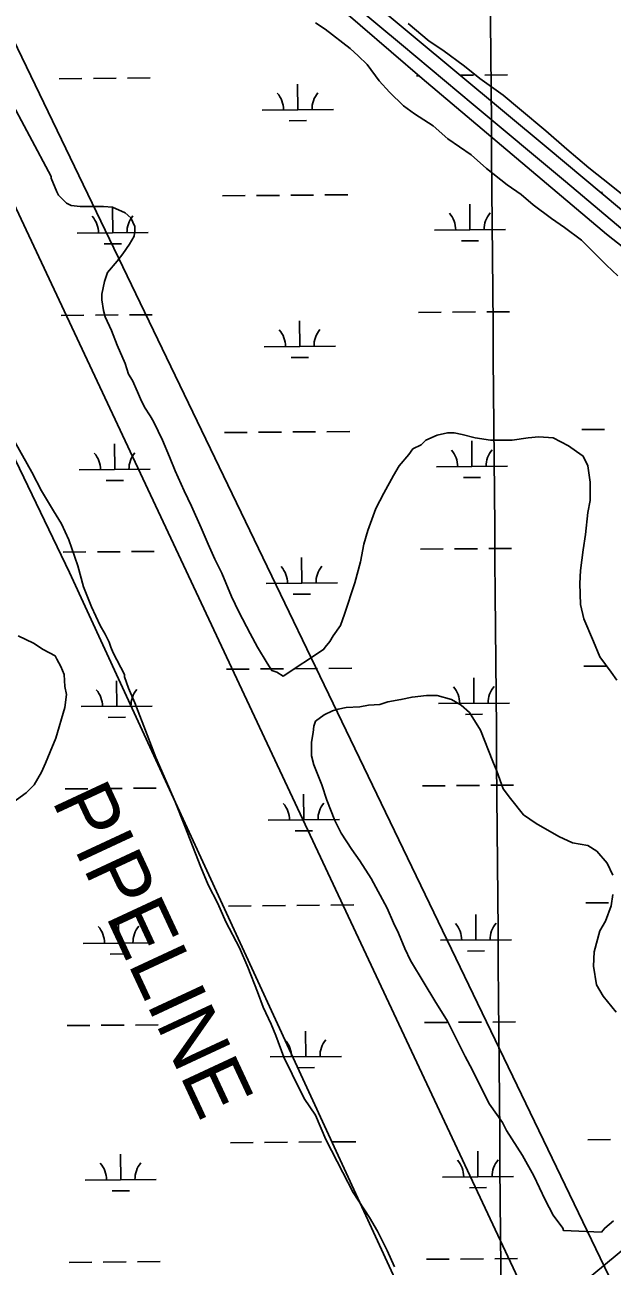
# Model space of a CAD drawing. Extents: x 3568792 to 3606828, y 529143 to 554785.
# Drawn here: x 3580902 to 3581727, y 542432 to 544177 of the extents above; entities that cross this region are included whole.
import ezdxf

# ---------------------------------------------------------------- set-up
doc = ezdxf.new("R2010")
doc.units = 0
for name, color, linetype in [('V-GRID-MAJR', 7, 'Continuous'), ('V-RAIL-TRAK', 7, 'Continuous'), ('V-SITE-VEGE', 7, 'Continuous'), ('V-UTIL-IDEN', 7, 'Continuous'), ('V-UTIL-LINE', 7, 'Continuous'), ('V-WETL-SWMP', 7, 'Continuous')]:
    doc.layers.add(name, color=color, linetype=linetype)

msp = doc.modelspace()

# ---------------------------------------------------------------- linework, layer by layer
at = {"layer": 'V-GRID-MAJR'}
msp.add_spline([(3581635.663, 534620.355), (3581585.44, 540678.077), (3581535.1920000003, 546738.885), (3581484.943, 552799.707), (3581484.918, 552802.775)], degree=3, dxfattribs=at)
at = {"layer": 'V-RAIL-TRAK'}
msp.add_lwpolyline([(3580851.771, 544633.429), (3580996.5270000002, 544512.45), (3581029.0840000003, 544485.449), (3581051.832, 544466.243), (3581133.9560000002, 544398.343), (3581292.914, 544264.992), (3581431.258, 544149.052), (3581532.038, 544064.734), (3581661.679, 543956.585), (3581805.061, 543836.0650000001), (3581938.3680000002, 543725.6240000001), (3582066.177, 543626.64), (3582144.055, 543569.356), (3582211.397, 543523.528)], dxfattribs=at)
at = {"layer": 'V-SITE-VEGE'}
for points in [[(3581310.598, 544179.824), (3581324.183, 544170.763), (3581359.279, 544143.584), (3581370.6010000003, 544133.395), (3581383.0530000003, 544120.9400000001), (3581400.0330000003, 544098.2930000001), (3581414.7490000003, 544082.439), (3581433.997, 544063.188), (3581449.846, 544051.865), (3581475.884, 544034.878), (3581496.264, 544016.758), (3581529.091, 543994.111), (3581550.6040000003, 543974.86), (3581580.039, 543952.213), (3581599.287, 543938.625), (3581616.267, 543923.903), (3581642.307, 543904.652), (3581660.419, 543892.194), (3581684.1950000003, 543874.076), (3581719.287, 543838.973), (3581735.139, 543824.252)], [(3581782.701, 543905.768), (3581726.097, 543951.062), (3581694.398, 543975.976), (3581663.829, 544002.02), (3581634.395, 544028.0650000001), (3581597.036, 544058.639), (3581574.393, 544077.893), (3581541.562, 544101.672), (3581520.052, 544118.654), (3581489.485, 544141.307), (3581470.238, 544153.763), (3581440.804, 544178.675)], [(3581420.345, 543543.5), (3581406.754, 543518.5920000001), (3581395.431, 543497.082), (3581384.103, 543466.511), (3581378.441, 543447.264), (3581373.9080000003, 543422.356), (3581365.98, 543392.919), (3581351.255, 543348.764), (3581345.593, 543332.912), (3581335.4, 543318.1950000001), (3581330.87, 543310.2710000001), (3581324.074, 543302.346), (3581321.811, 543298.95), (3581265.194, 543261.595), (3581256.1380000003, 543267.255), (3581249.345, 543269.52), (3581242.554, 543279.711), (3581228.969, 543302.358), (3581218.778, 543321.607), (3581202.933, 543352.18), (3581192.748, 543373.694), (3581179.164, 543406.53), (3581168.975, 543425.779), (3581159.921, 543447.2930000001), (3581149.734, 543469.938), (3581136.1520000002, 543500.508), (3581125.963, 543522.022), (3581113.511, 543550.33), (3581105.59, 543569.579), (3581095.403, 543593.356), (3581089.742, 543605.812), (3581082.951, 543619.399), (3581078.423, 543627.326), (3581070.4990000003, 543639.78), (3581064.838, 543651.104), (3581060.3140000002, 543661.295), (3581053.519, 543677.1460000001), (3581047.861, 543686.204), (3581043.332, 543700.925), (3581032.015, 543726.968), (3581024.091, 543747.349), (3581015.035, 543766.5970000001), (3581012.772, 543775.657), (3581010.509, 543790.376), (3581010.511, 543798.3), (3581013.909, 543816.416), (3581018.441, 543828.87), (3581032.029, 543844.72), (3581039.955, 543854.908), (3581049.0160000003, 543868.495), (3581055.809, 543879.814), (3581056.9450000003, 543887.742), (3581056.9450000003, 543893.403), (3581051.285, 543905.854), (3581043.359, 543912.652), (3581025.242, 543920.58), (3581012.791, 543921.712), (3580979.955, 543921.716), (3580967.501, 543922.851), (3580960.708, 543926.248), (3580949.389, 543937.572), (3580947.1240000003, 543942.102), (3580939.2, 543961.349), (3580939.202, 543963.6140000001), (3580878.075, 544077.977)], [(3580819.156, 543737.183), (3580823.684, 543731.523), (3580832.7430000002, 543722.462), (3580842.927, 543696.422), (3580853.116, 543672.643), (3580873.49, 543621.6900000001), (3580888.205, 543591.118), (3580911.9760000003, 543548.091), (3580925.558, 543522.049), (3580942.538, 543493.74), (3580953.859, 543475.623), (3580964.046, 543452.976), (3580976.498, 543416.745), (3580984.4220000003, 543387.305)], [(3581733.936, 543255.875), (3581726.0130000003, 543267.198), (3581710.161, 543288.712), (3581701.107, 543310.224), (3581687.525, 543341.929), (3581682.9990000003, 543362.309), (3581681.87, 543391.747), (3581683.005, 543409.8640000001), (3581686.404, 543439.302), (3581689.804, 543460.816), (3581693.2060000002, 543491.382), (3581696.603, 543508.366), (3581696.608, 543534.407), (3581693.214, 543557.051), (3581686.423, 543570.64), (3581677.365, 543577.433), (3581666.043, 543585.361), (3581644.531, 543596.686), (3581624.151, 543597.821), (3581609.432, 543596.6900000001), (3581586.788, 543593.297), (3581556.217, 543593.301), (3581534.707, 543596.699), (3581516.59, 543601.231), (3581505.269, 543603.496), (3581496.213, 543603.498), (3581481.492, 543600.102), (3581465.64, 543593.311), (3581458.845, 543586.518), (3581447.524, 543580.859), (3581441.861, 543572.934), (3581428.272, 543557.084), (3581420.345, 543543.5)], [(3580984.4220000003, 543387.305), (3580995.737, 543358.997), (3581008.1890000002, 543332.955), (3581014.98, 543320.4990000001), (3581020.6410000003, 543309.178), (3581022.904, 543302.385), (3581026.299, 543294.459), (3581042.147, 543263.886), (3581042.147, 543260.4890000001), (3581047.805, 543244.637), (3581056.861, 543224.255), (3581073.839, 543178.966), (3581086.289, 543147.261), (3581104.4, 543105.365), (3581113.4560000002, 543084.987), (3581127.036, 543051.017), (3581149.6750000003, 542993.27), (3581159.862, 542968.36), (3581173.446, 542942.318), (3581184.7630000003, 542916.275), (3581204.008, 542880.042), (3581215.328, 542852.865), (3581228.91, 542817.764), (3581236.832, 542796.252), (3581248.151, 542772.475), (3581254.9420000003, 542756.621), (3581266.261, 542726.051), (3581277.5810000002, 542702.2710000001), (3581294.561, 542668.301), (3581310.4080000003, 542644.524), (3581325.123, 542610.556), (3581348.894, 542564.132), (3581363.609, 542535.824), (3581386.25, 542500.724), (3581397.569, 542481.473), (3581411.151, 542454.2980000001), (3581421.34, 542431.653)], [(3580880.215, 543080.486), (3580903.9930000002, 543097.466), (3580915.318, 543108.785), (3580925.511, 543126.902), (3580931.174, 543139.354), (3580937.969, 543155.205), (3580945.897, 543174.452), (3580958.355, 543217.475), (3580960.622, 543235.589), (3580958.361, 543246.9130000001), (3580957.23, 543263.897), (3580952.702, 543275.22), (3580947.042, 543285.411), (3580944.779, 543289.939), (3580927.7970000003, 543298.9990000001), (3580914.21, 543308.058), (3580892.7, 543318.25)], [(3581334.255, 543212.899), (3581342.181, 543215.162), (3581353.502, 543217.425), (3581372.751, 543218.556), (3581385.205, 543220.817), (3581401.057, 543221.949), (3581412.38, 543225.345), (3581430.497, 543228.7390000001), (3581446.348, 543232.132), (3581466.728, 543234.395), (3581481.447, 543234.393), (3581501.826, 543228.73), (3581515.413, 543220.803), (3581526.732, 543210.612), (3581542.582, 543185.7), (3581559.559, 543141.541), (3581565.218, 543127.954), (3581574.272, 543103.045), (3581584.461, 543089.456), (3581602.576, 543066.809), (3581620.688, 543054.351), (3581652.389, 543036.233), (3581671.636, 543027.172), (3581693.146, 543023.773), (3581705.602, 543015.8470000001), (3581720.3170000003, 542998.861), (3581728.241, 542981.877)], [(3581729.312, 542496.151), (3581716.858, 542485.964), (3581712.328, 542480.301), (3581659.115, 542482.572), (3581657.982, 542485.97), (3581644.398, 542504.087), (3581633.079, 542525.601), (3581617.231, 542559.571), (3581601.384, 542587.878), (3581578.745, 542622.979), (3581573.082, 542634.302), (3581554.972, 542660.3470000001), (3581545.916, 542677.331), (3581531.201, 542707.901), (3581521.0100000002, 542727.151), (3581496.108, 542776.9720000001), (3581477.998, 542805.28), (3581463.281, 542830.192), (3581444.038, 542861.899), (3581436.114, 542878.881), (3581427.058, 542900.393), (3581420.267, 542915.1140000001), (3581411.211, 542935.4940000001), (3581388.574, 542977.39), (3581372.725, 543002.299), (3581361.403, 543018.153), (3581346.688, 543040.8), (3581337.632, 543058.916), (3581326.315, 543087.224), (3581319.524, 543108.736), (3581308.204, 543137.0430000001), (3581304.809, 543149.497), (3581304.811, 543168.746), (3581307.08, 543182.333), (3581308.21, 543191.389), (3581310.4760000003, 543198.182), (3581322.932, 543207.241), (3581334.255, 543212.899)], [(3581728.239, 542954.704), (3581725.972, 542938.852), (3581718.044, 542917.34), (3581710.116, 542903.756), (3581702.186, 542874.318), (3581701.052, 542853.938), (3581705.578, 542827.8960000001), (3581714.632, 542812.044), (3581732.747, 542789.397)]]:
    msp.add_lwpolyline(points, dxfattribs=at)
at = {"layer": 'V-UTIL-LINE'}
for points in [[(3576104.455, 549614.54), (3575980.615, 549380.701), (3575975.626, 549330.036), (3575795.666, 548982.226), (3575847.038, 548939.277), (3577996.318, 547114.274), (3577969.606, 547146.5380000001), (3578424.397, 546757.6410000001), (3580608.2060000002, 544894.199), (3580586.223, 544823.942), (3580566.441, 544763.821), (3580835.9560000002, 544259.362), (3581735.407, 542392.716), (3581735.411, 542392.049), (3583243.878, 539198.559), (3583455.717, 538592.296), (3583631.009, 538180.394), (3585262.885397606, 534650.9548145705)], [(3585128.275264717, 534649.8192223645), (3583719.583, 537704.209), (3582542.505, 540395.462), (3580772.2260000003, 544169.545), (3580472.688, 544757.343), (3580549.244, 544846.0480000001), (3580609.068, 544913.133), (3580567.3850000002, 544989.093), (3578476.0870000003, 546727.515), (3578101.464, 547060.86), (3578033.7660000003, 547070.019), (3577965.6780000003, 547126.361), (3576392.603, 548421.705), (3576369.895, 548541.527), (3575884.164, 548880.2660000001), (3575580.12, 549146.928), (3575181.362, 549483.568), (3575183.417, 549530.056)], [(3580613.684734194, 544136.940699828), (3580964.770032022, 543407.4351588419), (3581516.1019293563, 542211.0465516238), (3581921.2891189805, 541354.1472654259), (3582238.881483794, 540665.280643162), (3582616.1867291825, 539900.9831717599), (3582941.5330784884, 539167.7056383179), (3583265.5994303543, 538481.90100993), (3583288.6693842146, 538443.2290872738), (3583363.888233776, 538253.5674665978), (3583745.1074713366, 537485.180003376), (3584083.525794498, 536767.4394388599), (3584210.786539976, 536519.0029357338), (3584467.5920263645, 535947.402078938)]]:
    msp.add_lwpolyline(points, dxfattribs=at)
at = {"layer": 'V-WETL-SWMP'}
for p, q in [((3580950.4369965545, 544101.1577353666), (3580982.4358521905, 544101.4276837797)), ((3580998.4352800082, 544101.5626579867), (3581030.4341356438, 544101.8326063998)), ((3581046.4335634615, 544101.9675806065), (3581078.432419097, 544102.2375290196)), ((3581285.660710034, 544057.5540968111), (3581285.3570105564, 544093.5528135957)), ((3581452.327047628, 544105.3917749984), (3581456.102640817, 544105.4236266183)), ((3581514.293494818, 544105.9394430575), (3581532.3777006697, 544106.0920048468)), ((3581548.377112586, 544106.2269789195), (3581580.3759364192, 544106.4969270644)), ((3581235.662498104, 544057.1323024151), (3581335.658921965, 544057.9758912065)), ((3581273.7913165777, 544042.0224161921), (3581297.790458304, 544042.2248775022)), ((3581179.8334614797, 543936.586052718), (3581211.8323171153, 543936.8560011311)), ((3581227.831744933, 543936.9909753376), (3581259.830600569, 543937.2609237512)), ((3581275.830028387, 543937.3958979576), (3581307.828884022, 543937.665846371)), ((3581323.82831184, 543937.8008205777), (3581355.8271674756, 543938.070768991)), ((3581711.81671955, 543941.0992248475), (3581713.7761982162, 543941.1157553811)), ((3581025.6750543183, 543884.5417406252), (3581025.37135484, 543920.5404574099)), ((3581527.5651053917, 543888.775780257), (3581527.261405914, 543924.7744970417)), ((3580975.676842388, 543884.1199462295), (3581075.6732662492, 543884.9635350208)), ((3581477.566893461, 543888.3539858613), (3581577.5633173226, 543889.1975746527)), ((3581013.805660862, 543869.0100600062), (3581037.8048025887, 543869.2125213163)), ((3581515.695711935, 543873.244099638), (3581539.6948536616, 543873.4465609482)), ((3580953.2434749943, 543768.494593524), (3580985.2423306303, 543768.7645419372)), ((3581001.2417584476, 543768.8995161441), (3581033.2406140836, 543769.1694645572)), ((3581049.240041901, 543769.3044387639), (3581081.2388975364, 543769.574387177)), ((3581288.467188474, 543724.8909549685), (3581288.1634889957, 543760.8896717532)), ((3581455.1335260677, 543772.7286331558), (3581487.1323817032, 543772.998581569)), ((3581503.131809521, 543773.1335557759), (3581535.1306651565, 543773.403504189)), ((3581551.1300929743, 543773.5384783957), (3581583.12894861, 543773.8084268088)), ((3581238.4689765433, 543724.4691605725), (3581338.465400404, 543725.312749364)), ((3581276.5977950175, 543709.3592743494), (3581300.5969367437, 543709.5617356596)), ((3581182.6399399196, 543603.9229108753), (3581214.638795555, 543604.1928592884)), ((3581230.6382233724, 543604.3278334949), (3581262.6370790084, 543604.5977819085)), ((3581278.6365068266, 543604.7327561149), (3581310.6353624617, 543605.0027045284)), ((3581326.6347902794, 543605.1376787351), (3581358.633645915, 543605.4076271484)), ((3581684.5299909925, 543608.156950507), (3581716.528846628, 543608.4268989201)), ((3581028.4815327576, 543551.8785987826), (3581028.17783328, 543587.8773155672)), ((3581530.3715838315, 543556.1126384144), (3581530.067884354, 543592.1113551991)), ((3580978.4833208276, 543551.4568043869), (3581078.479744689, 543552.3003931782)), ((3581480.3733719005, 543555.6908440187), (3581580.369795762, 543556.53443281)), ((3581016.6121393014, 543536.3469181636), (3581040.611281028, 543536.5493794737)), ((3581518.502190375, 543540.5809577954), (3581542.501332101, 543540.7834191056)), ((3580956.049953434, 543435.8314516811), (3580988.0488090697, 543436.1014000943)), ((3581004.048236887, 543436.2363743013), (3581036.0470925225, 543436.5063227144)), ((3581052.0465203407, 543436.6412969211), (3581084.0453759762, 543436.9112453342)), ((3581457.940004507, 543440.065491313), (3581489.9388601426, 543440.3354397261)), ((3581505.938287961, 543440.470413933), (3581537.937143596, 543440.7403623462)), ((3581553.936571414, 543440.8753365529), (3581585.9354270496, 543441.145284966)), ((3581291.273666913, 543392.2278131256), (3581290.969967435, 543428.2265299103)), ((3581241.2754549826, 543391.8060187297), (3581341.2718788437, 543392.649607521)), ((3581279.4042734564, 543376.6961325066), (3581303.403415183, 543376.8985938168)), ((3581233.444701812, 543271.664691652), (3581265.4435574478, 543271.9346400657)), ((3581281.442985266, 543272.0696142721), (3581313.4418409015, 543272.3395626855)), ((3581329.441268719, 543272.4745368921), (3581361.4401243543, 543272.7444853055)), ((3581687.336469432, 543275.4938086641), (3581719.3353250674, 543275.7637570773)), ((3581031.2880111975, 543219.2154569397), (3581030.98431172, 543255.2141737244)), ((3581185.446418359, 543271.2597690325), (3581217.4452739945, 543271.5297174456)), ((3581533.1780622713, 543223.4494965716), (3581532.874362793, 543259.4482133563)), ((3580981.289799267, 543218.793662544), (3581081.2862231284, 543219.6372513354)), ((3581483.1798503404, 543223.0277021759), (3581583.1762742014, 543223.8712909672)), ((3581019.418617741, 543203.6837763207), (3581043.4177594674, 543203.8862376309)), ((3581521.3086688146, 543207.9178159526), (3581545.307810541, 543208.1202772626)), ((3580958.8564318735, 543103.1683098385), (3580990.8552875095, 543103.4382582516)), ((3581006.8547153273, 543103.5732324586), (3581038.8535709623, 543103.8431808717)), ((3581054.8529987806, 543103.9781550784), (3581086.851854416, 543104.2481034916)), ((3581460.746482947, 543107.4023494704), (3581492.745338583, 543107.6722978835)), ((3581508.7447664, 543107.8072720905), (3581540.743622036, 543108.0772205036)), ((3581556.7430498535, 543108.2121947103), (3581588.741905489, 543108.4821431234)), ((3581294.080145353, 543059.564671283), (3581293.7764458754, 543095.5633880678)), ((3581244.0819334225, 543059.1428768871), (3581344.0783572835, 543059.9864656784)), ((3581282.2107518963, 543044.032990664), (3581306.209893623, 543044.2354519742)), ((3581690.142947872, 542942.8306668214), (3581722.1418035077, 542943.1006152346)), ((3581188.252896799, 542938.5966271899), (3581220.2517524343, 542938.866575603)), ((3581236.251180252, 542939.0015498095), (3581268.2500358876, 542939.2714982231)), ((3581284.249463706, 542939.4064724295), (3581316.248319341, 542939.6764208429)), ((3581332.247747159, 542939.8113950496), (3581364.2466027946, 542940.0813434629)), ((3581535.9845407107, 542890.786354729), (3581535.6808412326, 542926.7850715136)), ((3581034.0944896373, 542886.5523150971), (3581033.7907901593, 542922.5510318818)), ((3581485.98632878, 542890.3645603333), (3581585.9827526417, 542891.2081491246)), ((3580984.0962777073, 542886.1305207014), (3581084.0927015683, 542886.9741094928)), ((3581022.225096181, 542871.0206344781), (3581046.2242379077, 542871.2230957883)), ((3581524.115147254, 542875.25467411), (3581548.1142889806, 542875.4571354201)), ((3580961.6629103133, 542770.5051679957), (3580993.6617659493, 542770.7751164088)), ((3581009.6611937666, 542770.9100906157), (3581041.660049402, 542771.1800390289)), ((3581057.6594772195, 542771.3150132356), (3581089.6583328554, 542771.5849616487)), ((3581463.5529613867, 542774.7392076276), (3581495.5518170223, 542775.0091560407)), ((3581511.5512448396, 542775.1441302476), (3581543.5501004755, 542775.4140786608)), ((3581559.5495282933, 542775.5490528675), (3581591.548383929, 542775.8190012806)), ((3581296.886623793, 542726.9015294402), (3581296.582924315, 542762.900246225)), ((3581246.8884118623, 542726.4797350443), (3581346.884835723, 542727.3233238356)), ((3581285.017230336, 542711.3698488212), (3581309.0163720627, 542711.5723101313)), ((3581692.9494263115, 542610.1675249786), (3581724.948281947, 542610.4374733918)), ((3581191.0593752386, 542605.9334853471), (3581223.058230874, 542606.2034337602)), ((3581239.0576586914, 542606.3384079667), (3581271.056514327, 542606.6083563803)), ((3581287.0559421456, 542606.7433305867), (3581319.0547977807, 542607.0132790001)), ((3581335.0542255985, 542607.1482532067), (3581367.053081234, 542607.4182016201)), ((3581538.7910191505, 542558.1232128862), (3581538.4873196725, 542594.1219296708)), ((3581036.9009680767, 542553.8891732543), (3581036.597268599, 542589.887890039)), ((3581488.7928072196, 542557.7014184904), (3581588.789231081, 542558.5450072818)), ((3580986.9027561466, 542553.4673788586), (3581086.899180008, 542554.3109676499)), ((3581526.921625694, 542542.591532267), (3581550.92076742, 542542.7939935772)), ((3581025.0315746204, 542538.3574926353), (3581049.030716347, 542538.5599539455)), ((3580964.469388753, 542437.8420261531), (3580996.4682443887, 542438.1119745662)), ((3581012.467672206, 542438.2469487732), (3581044.4665278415, 542438.5168971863)), ((3581060.4659556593, 542438.651871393), (3581092.4648112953, 542438.9218198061)), ((3581466.359439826, 542442.0760657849), (3581498.3582954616, 542442.346014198)), ((3581514.3577232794, 542442.480988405), (3581546.356578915, 542442.7509368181)), ((3581562.356006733, 542442.8859110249), (3581594.3548623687, 542443.155859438))]:
    msp.add_line(p, q, dxfattribs=at)
for points in [[(3581199.132, 544326.657), (3581460.569, 544101.578), (3581719.273, 543882.877), (3582150.148, 543542.974)], [(3581863.588, 543813.76), (3581637.677, 544003.301), (3581383.5270000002, 544214.713)], [(3581906.727, 542591.8640000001), (3581649.769, 542378.719)]]:
    msp.add_lwpolyline(points, dxfattribs=at)
for centre, radius, start, end in [((3581230.41574401, 544057.5628598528), 35.24628790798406, 359.71152644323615, 41.255184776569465), ((3581340.8976650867, 544058.4949062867), 35.246287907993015, 139.7115236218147, 181.25518195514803), ((3580970.4300882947, 543884.5505036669), 35.24628790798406, 359.71152644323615, 41.255184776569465), ((3581080.9120093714, 543885.482550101), 35.246287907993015, 139.7115236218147, 181.25518195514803), ((3581472.320139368, 543888.7845432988), 35.24628790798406, 359.71152644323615, 41.255184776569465), ((3581582.802060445, 543889.7165897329), 35.246287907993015, 139.7115236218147, 181.25518195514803), ((3581233.2222224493, 543724.8997180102), 35.24628790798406, 359.71152644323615, 41.255184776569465), ((3581343.704143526, 543725.8317644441), 35.246287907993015, 139.7115236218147, 181.25518195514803), ((3580973.2365667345, 543551.8873618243), 35.24628790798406, 359.71152644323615, 41.255184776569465), ((3581083.7184878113, 543552.8194082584), 35.246287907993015, 139.7115236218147, 181.25518195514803), ((3581475.1266178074, 543556.1214014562), 35.24628790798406, 359.71152644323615, 41.255184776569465), ((3581585.608538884, 543557.0534478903), 35.246287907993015, 139.7115236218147, 181.25518195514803), ((3581236.0287008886, 543392.2365761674), 35.24628790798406, 359.71152644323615, 41.255184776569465), ((3581346.5106219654, 543393.1686226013), 35.246287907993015, 139.7115236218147, 181.25518195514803), ((3580976.043045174, 543219.2242199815), 35.24628790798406, 359.71152644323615, 41.255184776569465), ((3581086.5249662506, 543220.1562664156), 35.246287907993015, 139.7115236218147, 181.25518195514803), ((3581477.933096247, 543223.4582596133), 35.24628790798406, 359.71152644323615, 41.255184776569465), ((3581588.4150173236, 543224.3903060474), 35.246287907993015, 139.7115236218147, 181.25518195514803), ((3581238.835179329, 543059.5734343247), 35.24628790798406, 359.71152644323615, 41.255184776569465), ((3581349.3171004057, 543060.5054807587), 35.246287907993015, 139.7115236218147, 181.25518195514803), ((3580978.8495236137, 542886.5610781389), 35.24628790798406, 359.71152644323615, 41.255184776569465), ((3581089.3314446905, 542887.493124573), 35.246287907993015, 139.7115236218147, 181.25518195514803), ((3581480.739574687, 542890.7951177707), 35.24628790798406, 359.71152644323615, 41.255184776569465), ((3581591.221495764, 542891.7271642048), 35.246287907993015, 139.7115236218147, 181.25518195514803), ((3581241.6416577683, 542726.9102924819), 35.24628790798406, 359.71152644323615, 41.255184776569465), ((3581352.123578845, 542727.8423389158), 35.246287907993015, 139.7115236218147, 181.25518195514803), ((3580981.6560020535, 542553.897936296), 35.24628790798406, 359.71152644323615, 41.255184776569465), ((3581092.1379231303, 542554.8299827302), 35.246287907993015, 139.7115236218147, 181.25518195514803), ((3581483.5460531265, 542558.1319759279), 35.24628790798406, 359.71152644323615, 41.255184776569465), ((3581594.027974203, 542559.064022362), 35.246287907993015, 139.7115236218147, 181.25518195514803)]:
    msp.add_arc(centre, radius, start, end, dxfattribs=at)

# ---------------------------------------------------------------- texts
at = {"layer": 'V-UTIL-IDEN'}
msp.add_text('PIPELINE', height=82.99983200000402, rotation=294.9689938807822, dxfattribs=at).set_placement((3580939.6040823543, 543086.9687997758))

doc.saveas('drawing.dxf')
